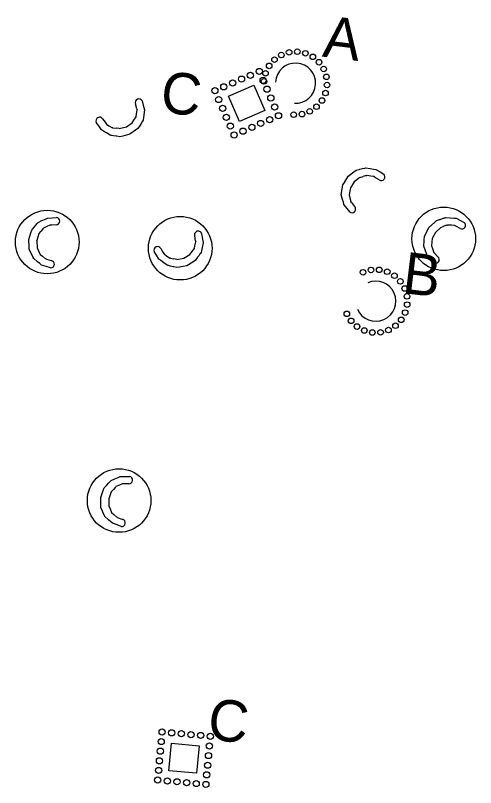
# Model space of a CAD drawing. Extents: x 2470000 to 2520000, y 340000 to 380000.
# Drawn here: x 2483183.7 to 2483350.2, y 365808.1 to 366087.8 of the extents above; entities that cross this region are included whole.
import ezdxf

# ---------------------------------------------------------------- set-up
doc = ezdxf.new("R2010")
doc.units = 0
for name, color, linetype in [('Coir Fiber Wattle with PAM Both CELL', 7, 'Continuous'), ('Coir Fiber Wattle with PAM Final CELL', 7, 'Continuous'), ('Label A Final CELL', 7, 'Continuous'), ('Label B CG CELL', 7, 'Continuous'), ('Prop Guardrail', 7, 'Continuous'), ('Prop Guardrail Anchor Unit CELL', 7, 'Continuous'), ('Prop Structure Anchor Unit CELL', 7, 'Continuous'), ('Rock Pipe Inlet Sediment Trap Type B CG CELL', 7, 'Continuous'), ('Rock Pipe Inlet Sediment Trap Type B Final CELL', 7, 'Continuous'), ('Scratch_Level_5', 7, 'Continuous'), ('Wattle Final CELL', 7, 'Continuous')]:
    doc.layers.add(name, color=color, linetype=linetype)

# ---------------------------------------------------------------- blocks, each defined once
blk = doc.blocks.new('C3')
at = {"layer": 'Prop Guardrail'}
blk.add_text('C', height=0.3, dxfattribs=at).set_placement((-0.161, -0.136))
blk = doc.blocks.new('A3')
at = {"layer": 'Label A Final CELL'}
blk.add_text('A', height=0.3, dxfattribs=at).set_placement((-0.133, -0.151))
blk = doc.blocks.new('B1')
at = {"layer": 'Label B CG CELL'}
blk.add_text('B', height=0.3, dxfattribs=at).set_placement((-0.1057, -0.151))
blk = doc.blocks.new('C2')
at = {"layer": 'Prop Guardrail Anchor Unit CELL'}
blk.add_text('C', height=0.3, dxfattribs=at).set_placement((-0.161, -0.136))

msp = doc.modelspace()

# ---------------------------------------------------------------- linework, layer by layer
at = {"layer": 'Coir Fiber Wattle with PAM Both CELL'}
for p, q in [((2483193.67, 366010.5), (2483192.98, 366009.64)), ((2483193.67, 366010.5), (2483193.82, 366010.68)), ((2483195.12, 366011.33), (2483193.82, 366010.68)), ((2483196.11, 366011.82), (2483195.12, 366011.33)), ((2483196.9, 366011.87), (2483196.11, 366011.82)), ((2483198.45, 366011.95), (2483196.9, 366011.87)), ((2483192.23, 366008.71), (2483191.46, 366006.2)), ((2483192.23, 366008.71), (2483192.98, 366009.64)), ((2483191.46, 366006.18), (2483191.46, 366006.2)), ((2483191.46, 366006.18), (2483191.57, 366003.64)), ((2483191.57, 366003.64), (2483192.08, 366002.55)), ((2483192.08, 366002.55), (2483192.69, 366001.24)), ((2483192.69, 366001.24), (2483193.48, 366000.58)), ((2483193.48, 366000.58), (2483194.61, 365999.64)), ((2483194.93, 365999.53), (2483194.61, 365999.64)), ((2483194.93, 365999.53), (2483196.7, 365998.97)), ((2483221.38, 365917.71), (2483220.06, 365917.12)), ((2483222.39, 365918.15), (2483221.38, 365917.71)), ((2483223.18, 365918.17), (2483222.39, 365918.15)), ((2483224.73, 365918.18), (2483223.18, 365918.17)), ((2483218.38, 365915.21), (2483217.5, 365912.73)), ((2483218.38, 365915.21), (2483219.16, 365916.11)), ((2483219.9, 365916.94), (2483219.16, 365916.11)), ((2483219.9, 365916.94), (2483220.06, 365917.12)), ((2483217.49, 365912.72), (2483217.5, 365912.73)), ((2483217.49, 365912.72), (2483217.5, 365910.18)), ((2483217.5, 365910.18), (2483217.96, 365909.07)), ((2483217.96, 365909.07), (2483218.51, 365907.73)), ((2483218.51, 365907.73), (2483219.27, 365907.04)), ((2483219.27, 365907.04), (2483220.36, 365906.04)), ((2483220.67, 365905.93), (2483220.36, 365906.04)), ((2483220.67, 365905.93), (2483222.42, 365905.28))]:
    msp.add_line(p, q, dxfattribs=at)
for points in [[(2483196.39, 365996.39), (2483194.89, 365996.84), (2483193.16, 365997.37), (2483192.51, 365997.9), (2483191.73, 365998.55), (2483190.35, 365999.69), (2483190.33, 365999.73), (2483190.14, 366000.12), (2483190.1, 366000.19), (2483189.68, 366001.05), (2483189.39, 366001.65), (2483188.74, 366002.96), (2483188.67, 366004), (2483188.51, 366006.55), (2483188.51, 366006.56), (2483189.31, 366009.07), (2483189.63, 366010.05), (2483190.36, 366010.91), (2483190.52, 366011.09), (2483191.14, 366011.82), (2483191.62, 366012.38), (2483191.73, 366012.5), (2483191.97, 366012.78), (2483191.97, 366012.79), (2483193.33, 366013.45), (2483194.54, 366014.03), (2483195.27, 366014.38), (2483197.03, 366014.5), (2483198.57, 366014.61)], [(2483221.99, 365902.72), (2483220.52, 365903.24), (2483218.81, 365903.85), (2483218.19, 365904.4), (2483217.43, 365905.08), (2483216.1, 365906.29), (2483216.09, 365906.32), (2483215.91, 365906.73), (2483215.88, 365906.8), (2483215.5, 365907.67), (2483215.23, 365908.28), (2483214.64, 365909.62), (2483214.62, 365910.67), (2483214.56, 365913.21), (2483214.57, 365913.23), (2483215.48, 365915.7), (2483215.84, 365916.67), (2483216.61, 365917.49), (2483216.77, 365917.67), (2483217.43, 365918.37), (2483217.93, 365918.9), (2483218.05, 365919.03), (2483218.3, 365919.3), (2483218.3, 365919.3), (2483219.69, 365919.9), (2483220.92, 365920.43), (2483221.67, 365920.75), (2483223.42, 365920.79), (2483224.97, 365920.83)]]:
    msp.add_lwpolyline(points, dxfattribs=at)
for centre in [(2483195.23, 366005.71), (2483221.24, 365912.08)]:
    msp.add_circle(centre, 11.5, dxfattribs=at)
for centre, radius, start, end in [((2483198.41, 366013.29), 1.33, 271.8897, 83.0023), ((2483196.54, 365997.68), 1.3, 263.0023, 83.0023), ((2483224.75, 365919.52), 1.33, 269.3732, 80.4859), ((2483222.2, 365904), 1.3, 260.4859, 80.4859)]:
    msp.add_arc(centre, radius, start, end, dxfattribs=at)
at = {"layer": 'Coir Fiber Wattle with PAM Final CELL'}
for p, q in [((2483337.64, 366010.97), (2483335.7, 366009.2)), ((2483337.64, 366010.97), (2483338.76, 366011.39)), ((2483339.8, 366011.78), (2483338.76, 366011.39)), ((2483339.8, 366011.78), (2483340.02, 366011.86)), ((2483341.46, 366011.76), (2483340.02, 366011.86)), ((2483342.57, 366011.68), (2483341.46, 366011.76)), ((2483343.27, 366011.32), (2483342.57, 366011.68)), ((2483344.65, 366010.6), (2483343.27, 366011.32)), ((2483248.93, 366006.08), (2483248.61, 366007.91)), ((2483335.69, 366009.19), (2483334.5, 366006.95)), ((2483335.69, 366009.19), (2483335.7, 366009.2)), ((2483248.68, 366004.3), (2483248.99, 366005.75)), ((2483248.93, 366006.08), (2483248.99, 366005.75)), ((2483334.38, 366005.75), (2483334.23, 366004.31)), ((2483334.5, 366006.95), (2483334.38, 366005.75)), ((2483236.31, 366003.4), (2483237.1, 366002.06)), ((2483237.1, 366002.06), (2483237.51, 366001.39)), ((2483246.86, 366001.19), (2483247.6, 366002.15)), ((2483247.6, 366002.15), (2483248.47, 366003.3)), ((2483248.47, 366003.3), (2483248.68, 366004.3)), ((2483334.23, 366004.31), (2483334.58, 366003.34)), ((2483334.58, 366003.34), (2483335.08, 366001.95)), ((2483335.3, 366001.7), (2483335.08, 366001.95)), ((2483335.3, 366001.7), (2483336.53, 366000.31)), ((2483237.51, 366001.39), (2483238.41, 366000.74)), ((2483238.41, 366000.74), (2483239.59, 365999.9)), ((2483239.82, 365999.85), (2483239.59, 365999.9)), ((2483239.82, 365999.85), (2483240.91, 365999.64)), ((2483242.08, 365999.41), (2483240.91, 365999.64)), ((2483242.08, 365999.41), (2483244.66, 365999.9)), ((2483244.67, 365999.9), (2483244.66, 365999.9)), ((2483244.67, 365999.9), (2483246.86, 366001.19))]:
    msp.add_line(p, q, dxfattribs=at)
for points in [[(2483334.95, 365998.25), (2483333.9, 365999.4), (2483332.67, 366000.74), (2483332.39, 366001.52), (2483332.04, 366002.48), (2483331.43, 366004.16), (2483331.44, 366004.2), (2483331.47, 366004.64), (2483331.47, 366004.72), (2483331.55, 366005.67), (2483331.6, 366006.34), (2483331.71, 366007.8), (2483332.18, 366008.73), (2483333.33, 366011), (2483333.34, 366011.01), (2483335.31, 366012.76), (2483336.08, 366013.45), (2483337.15, 366013.81), (2483337.38, 366013.89), (2483338.29, 366014.2), (2483338.98, 366014.44), (2483339.14, 366014.49), (2483339.49, 366014.61), (2483339.5, 366014.61), (2483341, 366014.49), (2483342.34, 366014.38), (2483343.15, 366014.31), (2483344.72, 366013.52), (2483346.1, 366012.83)], [(2483251.03, 366008.84), (2483251.33, 366007.3), (2483251.67, 366005.52), (2483251.5, 366004.7), (2483251.3, 366003.71), (2483250.93, 366001.96), (2483250.91, 366001.92), (2483250.65, 366001.57), (2483250.61, 366001.5), (2483250.04, 366000.73), (2483249.65, 366000.19), (2483248.79, 365999.01), (2483247.9, 365998.46), (2483245.73, 365997.13), (2483245.72, 365997.12), (2483243.12, 365996.66), (2483242.11, 365996.48), (2483241, 365996.73), (2483240.77, 365996.78), (2483239.83, 365997), (2483239.12, 365997.16), (2483238.96, 365997.2), (2483238.6, 365997.28), (2483238.59, 365997.28), (2483237.37, 365998.18), (2483236.29, 365998.97), (2483235.64, 365999.45), (2483234.72, 366000.95), (2483233.9, 366002.26)]]:
    msp.add_lwpolyline(points, dxfattribs=at)
for centre in [(2483338.69, 366006.86), (2483243.34, 366003.46)]:
    msp.add_circle(centre, 11.5, dxfattribs=at)
for centre, radius, start, end in [((2483345.29, 366011.77), 1.33, 241.3104, 52.4231), ((2483249.82, 366008.37), 1.3, 20.8264, 200.8264), ((2483235.15, 366002.74), 1.33, 29.7138, 200.8264), ((2483335.74, 365999.28), 1.3, 232.4231, 52.4231)]:
    msp.add_arc(centre, radius, start, end, dxfattribs=at)
at = {"layer": 'Prop Structure Anchor Unit CELL'}
msp.add_lwpolyline([(2483240.18, 365824.2), (2483250.14, 365823.29), (2483249.23, 365813.33), (2483239.28, 365814.25)], close=True, dxfattribs=at)
for centre in [(2483236.79, 365828.29), (2483240.27, 365827.97), (2483243.76, 365827.65), (2483247.24, 365827.33), (2483236.47, 365824.8), (2483250.73, 365827.02), (2483254.21, 365826.7), (2483253.89, 365823.21), (2483236.15, 365821.32), (2483253.58, 365819.73), (2483235.83, 365817.83), (2483253.26, 365816.24), (2483235.51, 365814.35), (2483235.19, 365810.86), (2483238.68, 365810.54), (2483252.94, 365812.75), (2483242.16, 365810.23), (2483245.65, 365809.91), (2483249.13, 365809.59), (2483252.62, 365809.27)]:
    msp.add_circle(centre, 1.12, dxfattribs=at)
at = {"layer": 'Rock Pipe Inlet Sediment Trap Type B CG CELL'}
for centre in [(2483312.36, 365995.59), (2483315.34, 365995.65), (2483309.5, 365994.75), (2483318.24, 365994.94), (2483320.85, 365993.5), (2483323.01, 365991.44), (2483324.55, 365988.89), (2483325.38, 365986.02), (2483325.44, 365983.04), (2483303.63, 365979.7), (2483324.73, 365980.14), (2483305.17, 365977.15), (2483323.3, 365977.53), (2483307.33, 365975.09), (2483309.94, 365973.65), (2483312.84, 365972.94), (2483315.82, 365973), (2483318.68, 365973.83), (2483321.23, 365975.38)]:
    msp.add_circle(centre, 1.01, dxfattribs=at)
msp.add_arc((2483314.09, 365984.29), 7.26, 203.7015, 113.6927, dxfattribs=at)
at = {"layer": 'Rock Pipe Inlet Sediment Trap Type B Final CELL'}
for centre in [(2483279.92, 366073.42), (2483282.74, 366074.4), (2483285.71, 366074.62), (2483288.64, 366074.07), (2483277.45, 366071.74), (2483291.33, 366072.77), (2483293.58, 366070.82), (2483275.51, 366069.49), (2483295.26, 366068.36), (2483274.21, 366066.8), (2483296.24, 366065.54), (2483273.65, 366063.87), (2483296.46, 366062.57), (2483295.91, 366059.64), (2483294.61, 366056.95), (2483292.66, 366054.69), (2483284.41, 366051.81), (2483287.38, 366052.03), (2483290.2, 366053.02)]:
    msp.add_circle(centre, 1.01, dxfattribs=at)
msp.add_arc((2483285.06, 366063.22), 7.26, 266.7332, 176.7243, dxfattribs=at)
at = {"layer": 'Scratch_Level_5'}
msp.add_lwpolyline([(2483260.83, 366058.55), (2483270.01, 366062.53), (2483273.99, 366053.36), (2483264.81, 366049.39)], close=True, dxfattribs=at)
for centre in [(2483268.73, 366066.09), (2483271.94, 366067.48), (2483262.31, 366063.3), (2483265.52, 366064.69), (2483273.34, 366064.27), (2483255.89, 366060.52), (2483259.1, 366061.91), (2483274.73, 366061.06), (2483257.28, 366057.31), (2483276.12, 366057.84), (2483258.67, 366054.1), (2483277.51, 366054.63), (2483260.06, 366050.88), (2483278.9, 366051.42), (2483272.48, 366048.64), (2483275.69, 366050.03), (2483261.46, 366047.67), (2483266.06, 366045.85), (2483269.27, 366047.25), (2483262.85, 366044.46)]:
    msp.add_circle(centre, 1.12, dxfattribs=at)
at = {"layer": 'Wattle Final CELL'}
for p, q in [((2483227.67, 366053.9), (2483227.21, 366055.7)), ((2483227.4, 366051.09), (2483227.55, 366052.11)), ((2483227.55, 366052.11), (2483227.75, 366053.57)), ((2483227.67, 366053.9), (2483227.75, 366053.57)), ((2483215.26, 366050.32), (2483216.16, 366049.05)), ((2483225.95, 366048.88), (2483226.61, 366049.88)), ((2483226.61, 366049.88), (2483227.4, 366051.09)), ((2483216.16, 366049.05), (2483216.61, 366048.4)), ((2483216.61, 366048.4), (2483217.55, 366047.82)), ((2483217.55, 366047.82), (2483218.79, 366047.06)), ((2483219.02, 366047.03), (2483218.79, 366047.06)), ((2483219.02, 366047.03), (2483220.12, 366046.9)), ((2483221.31, 366046.76), (2483220.12, 366046.9)), ((2483221.31, 366046.76), (2483223.85, 366047.43)), ((2483223.86, 366047.43), (2483223.85, 366047.43)), ((2483223.86, 366047.43), (2483225.95, 366048.88)), ((2483310.59, 366029.74), (2483309.52, 366029.44)), ((2483310.59, 366029.74), (2483310.81, 366029.81)), ((2483312.25, 366029.59), (2483310.81, 366029.81)), ((2483313.34, 366029.42), (2483312.25, 366029.59)), ((2483306.28, 366027.5), (2483304.91, 366025.36)), ((2483306.28, 366027.5), (2483306.29, 366027.51)), ((2483308.37, 366029.12), (2483306.29, 366027.51)), ((2483308.37, 366029.12), (2483309.52, 366029.44)), ((2483314.01, 366029), (2483313.34, 366029.42)), ((2483315.32, 366028.17), (2483314.01, 366029)), ((2483304.69, 366024.18), (2483304.43, 366022.75)), ((2483304.91, 366025.36), (2483304.69, 366024.18)), ((2483304.43, 366022.75), (2483304.7, 366021.76)), ((2483304.7, 366021.76), (2483305.08, 366020.33)), ((2483305.28, 366020.06), (2483305.08, 366020.33)), ((2483305.28, 366020.06), (2483306.4, 366018.58))]:
    msp.add_line(p, q, dxfattribs=at)
for points in [[(2483229.57, 366056.79), (2483229.97, 366055.29), (2483230.44, 366053.53), (2483230.33, 366052.71), (2483230.2, 366051.7), (2483229.96, 366049.93), (2483229.94, 366049.89), (2483229.7, 366049.52), (2483229.66, 366049.45), (2483229.16, 366048.64), (2483228.8, 366048.08), (2483228.03, 366046.83), (2483227.18, 366046.22), (2483225.11, 366044.74), (2483225.1, 366044.73), (2483222.54, 366044.09), (2483221.54, 366043.84), (2483220.43, 366044.01), (2483220.19, 366044.04), (2483219.24, 366044.19), (2483218.52, 366044.3), (2483218.35, 366044.33), (2483217.99, 366044.38), (2483217.98, 366044.38), (2483216.7, 366045.19), (2483215.57, 366045.91), (2483214.88, 366046.34), (2483213.85, 366047.76), (2483212.94, 366049.02)], [(2483304.65, 366016.66), (2483303.69, 366017.89), (2483302.58, 366019.32), (2483302.36, 366020.13), (2483302.1, 366021.11), (2483301.63, 366022.84), (2483301.63, 366022.88), (2483301.7, 366023.31), (2483301.71, 366023.39), (2483301.87, 366024.33), (2483301.97, 366024.99), (2483302.2, 366026.44), (2483302.75, 366027.32), (2483304.08, 366029.5), (2483304.09, 366029.51), (2483306.2, 366031.09), (2483307.02, 366031.71), (2483308.12, 366031.99), (2483308.35, 366032.05), (2483309.28, 366032.28), (2483309.99, 366032.46), (2483310.15, 366032.5), (2483310.51, 366032.59), (2483310.52, 366032.59), (2483312.01, 366032.34), (2483313.33, 366032.12), (2483314.13, 366031.99), (2483315.63, 366031.08), (2483316.96, 366030.27)]]:
    msp.add_lwpolyline(points, dxfattribs=at)
for centre, radius, start, end in [((2483228.39, 366056.25), 1.3, 24.9054, 204.9054), ((2483214.15, 366049.58), 1.33, 33.7928, 204.9054), ((2483316.06, 366029.28), 1.33, 236.6172, 47.7299), ((2483305.52, 366017.62), 1.3, 227.7299, 47.7299)]:
    msp.add_arc(centre, radius, start, end, dxfattribs=at)

# ---------------------------------------------------------------- block references
at = {"layer": 'Label A Final CELL', "xscale": 50.00000000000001, "yscale": 49.99999999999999, "rotation": -6.997703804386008}
msp.add_blockref('A3', (2483301.99, 366079.56), dxfattribs=at)
at = {"layer": 'Label B CG CELL', "xscale": 50, "yscale": 50, "rotation": -6.997703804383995}
msp.add_blockref('B1', (2483329.48, 365994.14), dxfattribs=at)
at = {"layer": 'Prop Structure Anchor Unit CELL', "xscale": 49.99999999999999, "yscale": 50.00000000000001, "rotation": -6.997703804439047}
msp.add_blockref('C2', (2483261.57, 365831.54), dxfattribs=at)
at = {"layer": 'Scratch_Level_5', "xscale": 49.99999999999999, "yscale": 50.00000000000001, "rotation": -6.997703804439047}
msp.add_blockref('C3', (2483244.49, 366058.64), dxfattribs=at)

doc.saveas('drawing.dxf')
